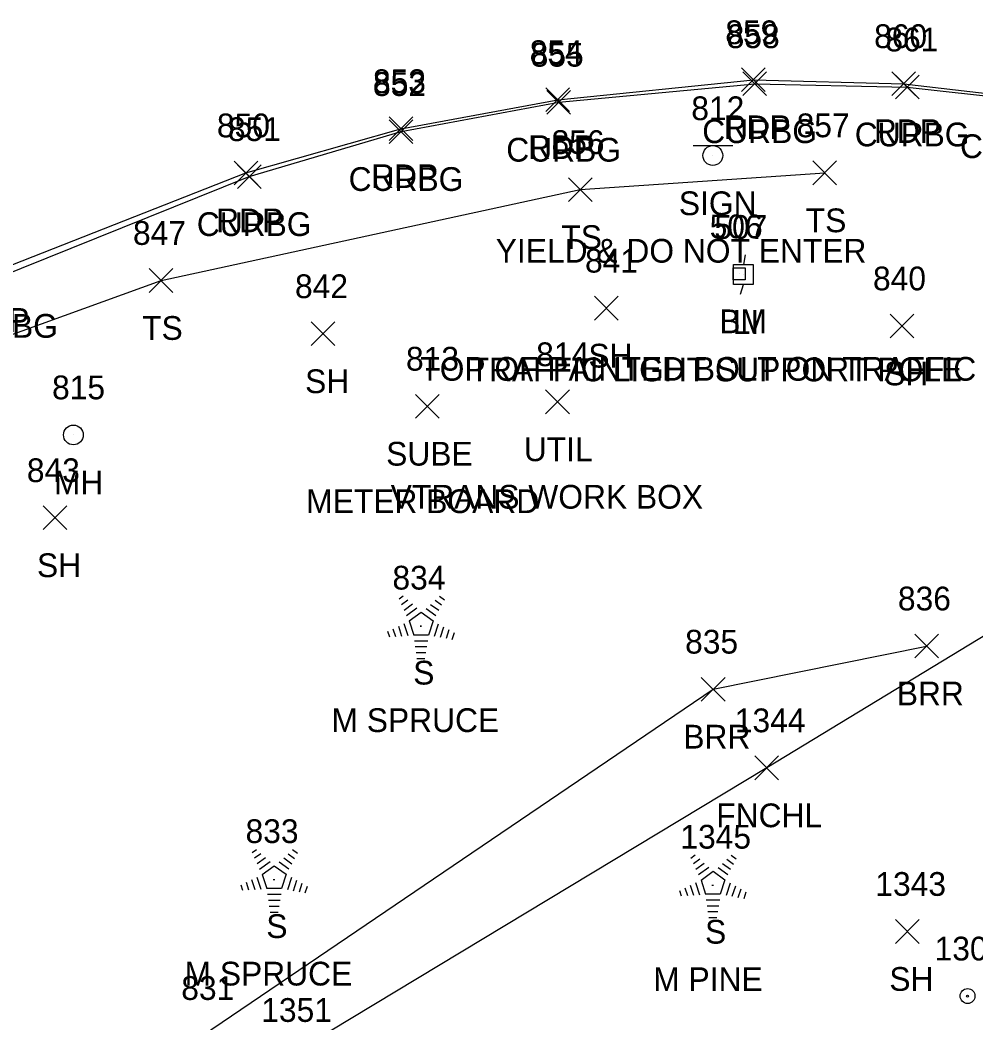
# Model space of a CAD drawing. Extents: x 1688195 to 1692013, y 424605 to 441234.
# Drawn here: x 1691718.1 to 1691798.5, y 439158.5 to 439242.9 of the extents above; entities that cross this region are included whole.
import ezdxf

# ---------------------------------------------------------------- set-up
doc = ezdxf.new("R2010")
doc.units = 0
for name, color, linetype in [('C_A', 7, 'Continuous'), ('C_C', 7, 'Continuous'), ('C_I', 7, 'Continuous'), ('CPBM', 7, 'Continuous'), ('L_A', 7, 'Continuous'), ('L_C', 7, 'Continuous'), ('L_I', 7, 'Continuous'), ('L_TIC', 7, 'Continuous'), ('LABL', 7, 'Continuous'), ('LELB', 7, 'Continuous'), ('LFNC', 7, 'Continuous'), ('LTC', 7, 'Continuous'), ('P_A', 7, 'Continuous'), ('P_I', 7, 'Continuous'), ('P_TIC', 7, 'Continuous'), ('PET', 7, 'Continuous'), ('R_A', 7, 'Continuous'), ('R_I', 7, 'Continuous'), ('R_TIC', 7, 'Continuous'), ('RC', 7, 'Continuous'), ('S_A', 7, 'Continuous'), ('S_C', 7, 'Continuous'), ('S_I', 7, 'Continuous'), ('SSGN', 7, 'Continuous'), ('U_A', 7, 'Continuous'), ('U_C', 7, 'Continuous'), ('U_I', 7, 'Continuous'), ('U_TIC', 7, 'Continuous'), ('UDEFAULT', 7, 'Continuous'), ('ULP', 7, 'Continuous'), ('UPGW', 7, 'Continuous'), ('UUMH', 7, 'Continuous')]:
    doc.layers.add(name, color=color, linetype=linetype)

msp = doc.modelspace()

# ---------------------------------------------------------------- linework, layer by layer
at = {"layer": 'CPBM'}
for p, q in [((1691778.111, 439221.053), (1691778.111, 439222.053)), ((1691778.111, 439222.053), (1691779.111, 439222.053)), ((1691779.111, 439222.053), (1691779.111, 439221.053)), ((1691778.614, 439221.554), (1691778.614, 439221.554)), ((1691778.614, 439221.554), (1691778.614, 439221.554)), ((1691779.111, 439221.053), (1691778.111, 439221.053))]:
    msp.add_line(p, q, dxfattribs=at)
at = {"layer": 'L_TIC'}
for points in [[(1691784.802, 439229.062), (1691786.802, 439231.062)], [(1691786.802, 439229.062), (1691784.802, 439231.062)], [(1691764.222, 439227.65), (1691766.222, 439229.65)], [(1691766.222, 439227.65), (1691764.222, 439229.65)], [(1691728.929, 439219.996), (1691730.929, 439221.996)], [(1691730.929, 439219.996), (1691728.929, 439221.996)], [(1691766.419, 439217.664), (1691768.419, 439219.664)], [(1691768.419, 439217.664), (1691766.419, 439219.664)], [(1691791.318, 439216.167), (1691793.318, 439218.167)], [(1691793.318, 439216.167), (1691791.318, 439218.167)], [(1691742.57, 439215.511), (1691744.57, 439217.511)], [(1691744.57, 439215.511), (1691742.57, 439217.511)], [(1691719.996, 439200.015), (1691721.996, 439202.015)], [(1691721.996, 439200.015), (1691719.996, 439202.015)], [(1691793.384, 439189.211), (1691795.384, 439191.211)], [(1691795.384, 439189.211), (1691793.384, 439191.211)], [(1691775.413, 439185.573), (1691777.413, 439187.573)], [(1691777.413, 439185.573), (1691775.413, 439187.573)], [(1691779.926, 439178.949), (1691781.926, 439180.949)], [(1691781.926, 439178.949), (1691779.926, 439180.949)], [(1691791.76, 439165.169), (1691793.76, 439167.169)], [(1691793.76, 439165.169), (1691791.76, 439167.169)]]:
    msp.add_lwpolyline(points, dxfattribs=at)
at = {"layer": 'LABL'}
msp.add_lwpolyline([(1691601.594, 439075.796), (1691600.489, 439085.06), (1691627.744, 439119.172), (1691640.706, 439127.558), (1691655.142, 439108.609), (1691685.11, 439134.919), (1691687.621, 439141.729), (1691698.904, 439155.756), (1691733.428, 439157.404), (1691776.413, 439186.573), (1691794.384, 439190.211)], dxfattribs=at)
at = {"layer": 'LELB'}
msp.add_lwpolyline([(1691494.972, 438989.23), (1691529.392, 439026.474), (1691563.115, 439061.461), (1691592.319, 439093.254), (1691622.448, 439123.566), (1691640.276, 439144.546), (1691642.631, 439146.185), (1691644.542, 439148.635), (1691657.136, 439160.248), (1691677.495, 439185.53), (1691687.795, 439198.064), (1691700.53, 439206.596), (1691711.711, 439214.402), (1691729.929, 439220.996), (1691765.222, 439228.65), (1691785.802, 439230.062)], dxfattribs=at)
at = {"layer": 'LFNC'}
msp.add_lwpolyline([(1691844.629, 439219.191), (1691827.301, 439208.177), (1691808.981, 439197.073), (1691805.179, 439194.785), (1691802.646, 439193.147), (1691780.926, 439179.949), (1691740.493, 439155.554), (1691707.63, 439134.904), (1691682.092, 439120.044), (1691638.963, 439093.47), (1691599.841, 439067.337), (1691566.38, 439033.383), (1691536.946, 439001.218), (1691500.893, 438961.261), (1691462.913, 438919.547), (1691429.394, 438883.141), (1691411.257, 438863.122)], dxfattribs=at)
at = {"layer": 'LTC'}
for p, q in [((1691749.97, 439194.174), (1691750.325, 439194.432)), ((1691750.18, 439193.709), (1691750.709, 439194.093)), ((1691753.369, 439194.415), (1691753.788, 439194.11)), ((1691750.39, 439193.243), (1691751.093, 439193.754)), ((1691750.599, 439192.777), (1691751.478, 439193.415)), ((1691752.255, 439193.37), (1691753.065, 439192.781)), ((1691752.627, 439193.718), (1691753.306, 439193.224)), ((1691752.998, 439194.066), (1691753.547, 439193.667)), ((1691750.824, 439192.322), (1691751.835, 439193.057)), ((1691751.835, 439193.057), (1691752.833, 439192.332)), ((1691749.458, 439191.67), (1691749.67, 439191.018)), ((1691749.914, 439191.887), (1691750.185, 439191.051)), ((1691750.369, 439192.103), (1691750.7, 439191.084)), ((1691750.824, 439192.322), (1691751.211, 439191.129)), ((1691752.833, 439192.332), (1691752.441, 439191.129)), ((1691753.27, 439192.061), (1691752.932, 439191.021)), ((1691753.715, 439191.811), (1691753.427, 439190.926)), ((1691754.159, 439191.561), (1691753.922, 439190.831)), ((1691749.003, 439191.453), (1691749.155, 439190.986)), ((1691752.441, 439191.129), (1691751.211, 439191.129)), ((1691754.603, 439191.31), (1691754.417, 439190.736)), ((1691752.403, 439190.629), (1691751.258, 439190.629)), ((1691752.319, 439190.129), (1691751.331, 439190.129)), ((1691752.235, 439189.629), (1691751.404, 439189.629)), ((1691752.152, 439189.129), (1691751.477, 439189.129)), ((1691737.602, 439172.825), (1691737.957, 439173.082)), ((1691741.001, 439173.065), (1691741.42, 439172.761)), ((1691737.812, 439172.359), (1691738.341, 439172.744)), ((1691738.022, 439171.894), (1691738.725, 439172.405)), ((1691740.259, 439172.369), (1691740.938, 439171.875)), ((1691740.629, 439172.717), (1691741.179, 439172.318)), ((1691774.542, 439172.354), (1691774.896, 439172.612)), ((1691774.751, 439171.889), (1691775.28, 439172.273)), ((1691777.569, 439172.246), (1691778.118, 439171.847)), ((1691777.94, 439172.595), (1691778.359, 439172.29)), ((1691738.231, 439171.428), (1691739.109, 439172.066)), ((1691738.456, 439170.973), (1691739.467, 439171.707)), ((1691739.467, 439171.707), (1691740.464, 439170.982)), ((1691739.887, 439172.02), (1691740.697, 439171.432)), ((1691774.961, 439171.423), (1691775.665, 439171.934)), ((1691775.17, 439170.957), (1691776.049, 439171.595)), ((1691776.827, 439171.55), (1691777.636, 439170.961)), ((1691777.198, 439171.898), (1691777.877, 439171.404)), ((1691737.546, 439170.537), (1691737.817, 439169.702)), ((1691738.001, 439170.754), (1691738.332, 439169.734)), ((1691738.456, 439170.973), (1691738.843, 439169.779)), ((1691740.464, 439170.982), (1691740.073, 439169.779)), ((1691740.902, 439170.712), (1691740.564, 439169.672)), ((1691741.347, 439170.461), (1691741.059, 439169.577)), ((1691775.395, 439170.502), (1691776.407, 439171.237)), ((1691775.395, 439170.502), (1691775.782, 439169.309)), ((1691776.407, 439171.237), (1691777.404, 439170.512)), ((1691777.404, 439170.512), (1691777.012, 439169.309)), ((1691736.635, 439170.104), (1691736.787, 439169.636)), ((1691737.09, 439170.321), (1691737.302, 439169.669)), ((1691740.073, 439169.779), (1691738.843, 439169.779)), ((1691741.791, 439170.211), (1691741.554, 439169.482)), ((1691742.235, 439169.961), (1691742.049, 439169.387)), ((1691773.574, 439169.633), (1691773.726, 439169.165)), ((1691774.03, 439169.85), (1691774.241, 439169.198)), ((1691774.485, 439170.067), (1691774.756, 439169.231)), ((1691774.94, 439170.283), (1691775.271, 439169.264)), ((1691777.841, 439170.241), (1691777.503, 439169.201)), ((1691778.286, 439169.99), (1691777.998, 439169.106)), ((1691778.73, 439169.74), (1691778.493, 439169.011)), ((1691740.035, 439169.279), (1691738.89, 439169.279)), ((1691739.951, 439168.779), (1691738.963, 439168.779)), ((1691777.012, 439169.309), (1691775.782, 439169.309)), ((1691776.974, 439168.809), (1691775.83, 439168.809)), ((1691779.175, 439169.49), (1691778.988, 439168.916)), ((1691739.867, 439168.279), (1691739.036, 439168.279)), ((1691776.89, 439168.309), (1691775.902, 439168.309)), ((1691739.784, 439167.779), (1691739.109, 439167.779)), ((1691776.807, 439167.809), (1691775.975, 439167.809)), ((1691776.723, 439167.309), (1691776.048, 439167.309))]:
    msp.add_line(p, q, dxfattribs=at)
at = {"layer": 'P_TIC'}
for points in [[(1691778.804, 439236.901), (1691780.804, 439238.901)], [(1691780.804, 439236.901), (1691778.804, 439238.901)], [(1691791.46, 439236.573), (1691793.46, 439238.573)], [(1691793.46, 439236.573), (1691791.46, 439238.573)], [(1691762.328, 439235.221), (1691764.328, 439237.221)], [(1691764.328, 439235.221), (1691762.328, 439237.221)], [(1691749.128, 439232.775), (1691751.128, 439234.775)], [(1691751.128, 439232.775), (1691749.128, 439234.775)], [(1691736.082, 439229.055), (1691738.082, 439231.055)], [(1691738.082, 439229.055), (1691736.082, 439231.055)]]:
    msp.add_lwpolyline(points, dxfattribs=at)
at = {"layer": 'PET'}
msp.add_lwpolyline([(1691715.714, 439221.672), (1691737.082, 439230.055), (1691750.128, 439233.775), (1691763.328, 439236.221), (1691779.804, 439237.901), (1691792.46, 439237.573), (1691804.318, 439236.191), (1691808.491, 439235.452), (1691812.042, 439235.195), (1691821.483, 439233.162), (1691827.737, 439231.575), (1691835.045, 439229.097), (1691845.28, 439224.601), (1691854.138, 439220.168), (1691861.506, 439215.423), (1691883.06, 439199.579), (1691888.13, 439193.66), (1691894.204, 439181.616), (1691894.95, 439171.633), (1691892.497, 439160.46), (1691888.634, 439152.728)], dxfattribs=at)
at = {"layer": 'R_TIC'}
for points in [[(1691778.913, 439236.569), (1691780.913, 439238.569)], [(1691780.913, 439236.569), (1691778.913, 439238.569)], [(1691791.753, 439236.293), (1691793.753, 439238.293)], [(1691793.753, 439236.293), (1691791.753, 439238.293)], [(1691762.412, 439235.009), (1691764.412, 439237.009)], [(1691764.412, 439235.009), (1691762.412, 439237.009)], [(1691749.141, 439232.54), (1691751.141, 439234.54)], [(1691751.141, 439232.54), (1691749.141, 439234.54)], [(1691736.358, 439228.742), (1691738.358, 439230.742)], [(1691738.358, 439228.742), (1691736.358, 439230.742)]]:
    msp.add_lwpolyline(points, dxfattribs=at)
at = {"layer": 'RC'}
msp.add_lwpolyline([(1691673.648, 439189.009), (1691697.785, 439210.208), (1691710.111, 439217.785), (1691716.003, 439221.174), (1691737.358, 439229.742), (1691750.141, 439233.54), (1691763.412, 439236.009), (1691779.913, 439237.569), (1691792.753, 439237.293), (1691801.61, 439236.306), (1691804.318, 439236.191)], dxfattribs=at)
at = {"layer": 'SSGN'}
for p, q in [((1691774.741, 439232.354), (1691778.074, 439232.354)), ((1691776.387, 439231.521), (1691776.387, 439231.521))]:
    msp.add_line(p, q, dxfattribs=at)
msp.add_circle((1691776.387, 439231.521), 0.833, dxfattribs=at)
at = {"layer": 'U_TIC'}
for points in [[(1691751.349, 439209.406), (1691753.349, 439211.406)], [(1691753.349, 439209.406), (1691751.349, 439211.406)]]:
    msp.add_lwpolyline(points, dxfattribs=at)
at = {"layer": 'UDEFAULT'}
for points in [[(1691762.307, 439209.779), (1691764.307, 439211.779)], [(1691764.307, 439209.779), (1691762.307, 439211.779)]]:
    msp.add_lwpolyline(points, dxfattribs=at)
at = {"layer": 'ULP'}
for p, q in [((1691779.121, 439223.168), (1691778.954, 439222.335)), ((1691778.121, 439220.668), (1691778.121, 439222.335)), ((1691778.121, 439222.335), (1691779.787, 439222.335)), ((1691779.787, 439222.335), (1691779.787, 439220.668)), ((1691778.954, 439221.502), (1691778.954, 439221.502)), ((1691779.787, 439220.668), (1691778.121, 439220.668)), ((1691778.704, 439219.835), (1691778.954, 439220.668))]:
    msp.add_line(p, q, dxfattribs=at)
at = {"layer": 'UPGW'}
for radius in [0.625, 0.0833]:
    msp.add_circle((1691797.828, 439160.728), radius, dxfattribs=at)
at = {"layer": 'UUMH'}
for p, q in [((1691722.55, 439207.991), (1691722.55, 439207.991)), ((1691723.383, 439207.991), (1691723.383, 439207.991))]:
    msp.add_line(p, q, dxfattribs=at)
msp.add_circle((1691722.55, 439207.991), 0.833, dxfattribs=at)

# ---------------------------------------------------------------- texts
at = {"layer": 'C_A'}
msp.add_text('BM', height=2, dxfattribs=at).set_placement((1691776.929, 439216.554))
at = {"layer": 'C_C'}
msp.add_text('TOP OF PAINTED BOLT ON TRAFFIC', height=2, dxfattribs=at).set_placement((1691751.756, 439212.554))
at = {"layer": 'C_I'}
msp.add_text('506', height=2, dxfattribs=at).set_placement((1691776.118, 439224.554))
at = {"layer": 'L_A'}
for s, p in [('TS', (1691784.211, 439225.062)), ('TS', (1691763.632, 439223.65)), ('TS', (1691728.338, 439215.996)), ('SH', (1691765.907, 439213.664)), ('SH', (1691742.058, 439211.511)), ('SH', (1691790.806, 439212.167)), ('SH', (1691719.484, 439196.015)), ('S', (1691751.161, 439186.966)), ('BRR', (1691791.872, 439185.211)), ('BRR', (1691773.902, 439181.573)), ('FNCHL', (1691776.674, 439174.949)), ('S', (1691738.793, 439165.617)), ('S', (1691775.732, 439165.146)), ('SH', (1691791.248, 439161.169))]:
    msp.add_text(s, height=2, dxfattribs=at).set_placement(p)
at = {"layer": 'L_C'}
for s, p in [('M SPRUCE', (1691744.279, 439182.966)), ('M SPRUCE', (1691731.911, 439161.617)), ('M PINE', (1691771.37, 439161.146))]:
    msp.add_text(s, height=2, dxfattribs=at).set_placement(p)
at = {"layer": 'L_I'}
for s, p in [('857', (1691783.44, 439233.062)), ('856', (1691762.805, 439231.65)), ('847', (1691727.567, 439223.996)), ('841', (1691765.624, 439221.664)), ('840', (1691789.869, 439220.167)), ('842', (1691741.208, 439219.511)), ('843', (1691718.633, 439204.015)), ('834', (1691749.413, 439194.966)), ('836', (1691791.967, 439193.211)), ('835', (1691774.051, 439189.573)), ('1344', (1691778.233, 439182.949)), ('833', (1691737.045, 439173.617)), ('1345', (1691773.654, 439173.146)), ('1343', (1691790.067, 439169.169)), ('831', (1691731.633, 439160.404)), ('1351', (1691738.367, 439158.554))]:
    msp.add_text(s, height=2, dxfattribs=at).set_placement(p)
at = {"layer": 'LTC'}
for p in [(1691751.718, 439192.07), (1691739.35, 439170.721), (1691776.289, 439170.25)]:
    msp.add_text('.', height=1.037, rotation=270, dxfattribs=at).set_placement(p)
at = {"layer": 'P_A'}
for p in [(1691777.292, 439232.901), (1691789.948, 439232.573), (1691760.816, 439231.221), (1691747.616, 439228.775), (1691734.57, 439225.055), (1691713.202, 439216.672)]:
    msp.add_text('RDP', height=2, dxfattribs=at).set_placement(p)
at = {"layer": 'P_I'}
for s, p in [('859', (1691777.434, 439240.901)), ('860', (1691789.964, 439240.573)), ('854', (1691760.965, 439239.221)), ('853', (1691747.766, 439236.775)), ('850', (1691734.633, 439233.055))]:
    msp.add_text(s, height=2, dxfattribs=at).set_placement(p)
at = {"layer": 'R_A'}
for p in [(1691775.496, 439232.569), (1691788.335, 439232.293), (1691758.994, 439231.009), (1691797.193, 439231.306), (1691745.723, 439228.54), (1691732.94, 439224.742), (1691711.586, 439216.174)]:
    msp.add_text('CURBG', height=2, dxfattribs=at).set_placement(p)
at = {"layer": 'R_I'}
for s, p in [('858', (1691777.551, 439240.569)), ('861', (1691790.91, 439240.293)), ('855', (1691761.049, 439239.009)), ('852', (1691747.778, 439236.54)), ('851', (1691735.562, 439232.742))]:
    msp.add_text(s, height=2, dxfattribs=at).set_placement(p)
at = {"layer": 'S_A'}
msp.add_text('SIGN', height=2, dxfattribs=at).set_placement((1691773.525, 439226.5))
at = {"layer": 'S_C'}
msp.add_text('YIELD & DO NOT ENTER', height=2, dxfattribs=at).set_placement((1691758.108, 439222.5))
at = {"layer": 'S_I'}
msp.add_text('812', height=2, dxfattribs=at).set_placement((1691774.573, 439234.5))
at = {"layer": 'U_A'}
for s, p in [('LI', (1691778.056, 439216.502)), ('UTIL', (1691760.473, 439205.779)), ('SUBE', (1691748.884, 439205.406)), ('MH', (1691720.912, 439202.991))]:
    msp.add_text(s, height=2, dxfattribs=at).set_placement(p)
at = {"layer": 'U_C'}
for s, p in [('TRAFFIC LIGHT SUPPORT POLE', (1691755.915, 439212.502)), ('METER BOARD', (1691742.152, 439201.406)), ('VTRANS WORK BOX', (1691749.26, 439201.779))]:
    msp.add_text(s, height=2, dxfattribs=at).set_placement(p)
at = {"layer": 'U_I'}
for s, p in [('507', (1691776.513, 439224.502)), ('813', (1691750.553, 439213.406)), ('814', (1691761.512, 439213.779)), ('815', (1691720.755, 439210.991)), ('1304', (1691795.056, 439163.728))]:
    msp.add_text(s, height=2, dxfattribs=at).set_placement(p)

doc.saveas('drawing.dxf')
